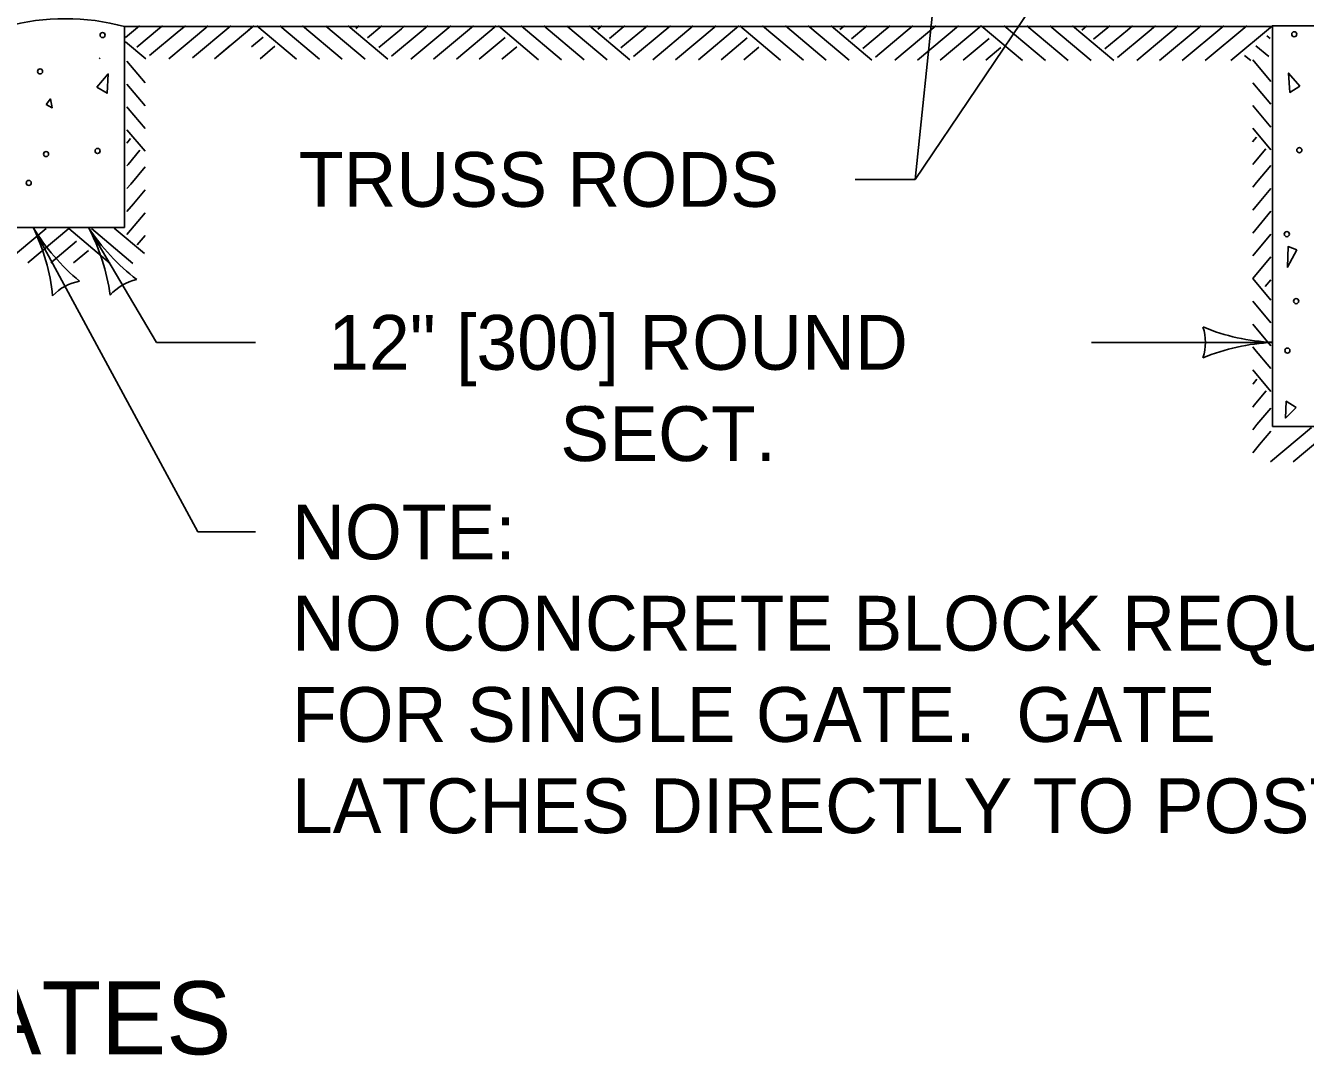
# Model space of a CAD drawing. Extents: x 49973.1 to 50021, y 49987.6 to 50015.4.
# Drawn here: x 50005.847 to 50007.249, y 49993.862 to 49994.99 of the extents above; entities that cross this region are included whole.
import ezdxf

# ---------------------------------------------------------------- set-up
doc = ezdxf.new("R2010")
doc.units = 0
for name, color, linetype in [('Level 1', 7, 'Continuous'), ('Level 2', 7, 'Continuous'), ('Level 3', 7, 'Continuous')]:
    doc.layers.add(name, color=color, linetype=linetype)

msp = doc.modelspace()

# ---------------------------------------------------------------- linework, layer by layer
at = {"layer": 'Level 1'}
for p, q in [((50007.2132, 49994.9895), (50005.9553, 49994.9895)), ((50005.9557, 49994.9894), (50005.9557, 49994.7693)), ((50005.9568, 49994.9774), (50005.9722, 49994.9902)), ((50005.9693, 49994.9669), (50005.9939, 49994.9875)), ((50005.9832, 49994.9575), (50006.0155, 49994.9846)), ((50005.9939, 49994.9875), (50005.9972, 49994.9902)), ((50006.0041, 49994.9541), (50006.0356, 49994.9804)), ((50006.0155, 49994.9846), (50006.0223, 49994.9902)), ((50006.0302, 49994.955), (50006.0723, 49994.9902)), ((50006.0356, 49994.9804), (50006.0473, 49994.9902)), ((50006.0541, 49994.9541), (50006.0972, 49994.9902)), ((50006.0915, 49994.9854), (50006.0972, 49994.9902)), ((50006.0946, 49994.9671), (50006.1075, 49994.9779)), ((50006.1442, 49994.9536), (50006.1007, 49994.9902)), ((50006.1692, 49994.9536), (50006.1257, 49994.9902)), ((50006.1942, 49994.9536), (50006.1507, 49994.9902)), ((50006.2192, 49994.9536), (50006.1762, 49994.9897)), ((50006.2442, 49994.9536), (50006.2007, 49994.9902)), ((50006.2092, 49994.9871), (50006.2129, 49994.9902)), ((50006.2219, 49994.9769), (50006.2376, 49994.99)), ((50006.2344, 49994.9664), (50006.259, 49994.987)), ((50006.2483, 49994.957), (50006.2806, 49994.9841)), ((50006.259, 49994.987), (50006.2629, 49994.9902)), ((50006.2692, 49994.9536), (50006.313, 49994.9902)), ((50006.2806, 49994.9841), (50006.288, 49994.9902)), ((50006.2942, 49994.9536), (50006.338, 49994.9902)), ((50006.3192, 49994.9536), (50006.3629, 49994.9902)), ((50006.3442, 49994.9536), (50006.3726, 49994.9774)), ((50006.4093, 49994.9531), (50006.3652, 49994.9902)), ((50006.4343, 49994.9531), (50006.3902, 49994.9902)), ((50006.4593, 49994.9531), (50006.4152, 49994.9902)), ((50006.4413, 49994.9892), (50006.4402, 49994.9902)), ((50006.4843, 49994.9531), (50006.4413, 49994.9892)), ((50006.5093, 49994.9531), (50006.4652, 49994.9902)), ((50006.4743, 49994.9866), (50006.4786, 49994.9902)), ((50006.487, 49994.9764), (50006.5027, 49994.9895)), ((50006.4995, 49994.9659), (50006.5241, 49994.9865)), ((50006.5027, 49994.9895), (50006.5036, 49994.9902)), ((50006.5134, 49994.9565), (50006.5457, 49994.9836)), ((50006.5241, 49994.9865), (50006.5286, 49994.9902)), ((50006.5343, 49994.9531), (50006.5787, 49994.9902)), ((50006.5457, 49994.9836), (50006.5537, 49994.9902)), ((50006.5593, 49994.9531), (50006.6037, 49994.9902)), ((50006.5843, 49994.9531), (50006.6286, 49994.9902)), ((50006.6093, 49994.9531), (50006.6377, 49994.9769)), ((50006.6744, 49994.9526), (50006.6297, 49994.9902)), ((50006.6994, 49994.9526), (50006.6547, 49994.9902)), ((50006.7244, 49994.9526), (50006.6797, 49994.9902)), ((50006.7064, 49994.9887), (50006.7047, 49994.9902)), ((50006.7494, 49994.9526), (50006.7064, 49994.9887)), ((50006.7744, 49994.9526), (50006.7297, 49994.9902)), ((50006.7394, 49994.9861), (50006.7444, 49994.9903)), ((50006.7521, 49994.9759), (50006.7678, 49994.989)), ((50006.7646, 49994.9654), (50006.7892, 49994.986)), ((50006.7678, 49994.989), (50006.7693, 49994.9902)), ((50006.7785, 49994.956), (50006.8108, 49994.9831)), ((50006.7892, 49994.986), (50006.7943, 49994.9902)), ((50006.7994, 49994.9526), (50006.8444, 49994.9902)), ((50006.8108, 49994.9831), (50006.8194, 49994.9902)), ((50006.8244, 49994.9526), (50006.8694, 49994.9902)), ((50006.8494, 49994.9526), (50006.8942, 49994.9902)), ((50006.9395, 49994.9521), (50006.8942, 49994.9902)), ((50006.9645, 49994.9521), (50006.9192, 49994.9902)), ((50006.9895, 49994.9521), (50006.9442, 49994.9902)), ((50006.9715, 49994.9882), (50006.9692, 49994.9902)), ((50007.0145, 49994.9521), (50006.9715, 49994.9882)), ((50007.0395, 49994.9521), (50006.9942, 49994.9902)), ((50007.0045, 49994.9856), (50007.0095, 49994.9898)), ((50007.0095, 49994.9898), (50007.01, 49994.9902)), ((50007.0172, 49994.9754), (50007.0329, 49994.9885)), ((50007.0297, 49994.9649), (50007.0543, 49994.9855)), ((50007.0329, 49994.9885), (50007.035, 49994.9902)), ((50007.0436, 49994.9555), (50007.0759, 49994.9826)), ((50007.0543, 49994.9855), (50007.06, 49994.9902)), ((50007.0645, 49994.9521), (50007.11, 49994.9902)), ((50007.0759, 49994.9826), (50007.0851, 49994.9902)), ((50007.0895, 49994.9521), (50007.135, 49994.9902)), ((50007.1145, 49994.9521), (50007.1599, 49994.9902)), ((50007.1395, 49994.9521), (50007.185, 49994.9902)), ((50007.1677, 49994.9522), (50007.2132, 49994.9903)), ((50007.2106, 49994.9764), (50007.2071, 49994.9793)), ((50007.2132, 49994.9903), (50007.2132, 49994.5512)), ((50007.2132, 49994.9903), (50007.3432, 49994.9903)), ((50005.9791, 49994.9541), (50005.9569, 49994.9728)), ((50006.0541, 49994.9541), (50006.0715, 49994.9687)), ((50006.1041, 49994.9541), (50006.1204, 49994.9678)), ((50006.3692, 49994.9536), (50006.3855, 49994.9673)), ((50006.6343, 49994.9531), (50006.6506, 49994.9668)), ((50006.8744, 49994.9526), (50006.9028, 49994.9764)), ((50006.8994, 49994.9526), (50006.9157, 49994.9663)), ((50007.2094, 49994.9564), (50007.195, 49994.9684)), ((50005.9291, 49994.9541), (50005.9278, 49994.9552)), ((50005.9782, 49994.9277), (50005.9583, 49994.9514)), ((50007.1895, 49994.9521), (50007.1827, 49994.9578)), ((50007.2115, 49994.9292), (50007.1916, 49994.9529)), ((50005.9782, 49994.9027), (50005.9583, 49994.9264)), ((50007.2115, 49994.9042), (50007.1916, 49994.9279)), ((50005.9598, 49994.8997), (50005.9583, 49994.9014)), ((50005.9782, 49994.8777), (50005.9598, 49994.8997)), ((50007.1931, 49994.9012), (50007.1916, 49994.9029)), ((50007.2115, 49994.8792), (50007.1931, 49994.9012)), ((50005.9624, 49994.8667), (50005.9582, 49994.8617)), ((50005.9782, 49994.8527), (50005.9583, 49994.8764)), ((50007.1957, 49994.8682), (50007.1915, 49994.8632)), ((50007.2115, 49994.8542), (50007.1916, 49994.8779)), ((50005.9726, 49994.854), (50005.9595, 49994.8383)), ((50007.2059, 49994.8555), (50007.1928, 49994.8398)), ((50005.9595, 49994.8383), (50005.9583, 49994.8368)), ((50007.1928, 49994.8398), (50007.1916, 49994.8383)), ((50007.2115, 49994.8371), (50007.1958, 49994.8184)), ((50005.9782, 49994.8356), (50005.9625, 49994.8169)), ((50005.9625, 49994.8169), (50005.9583, 49994.8118)), ((50005.9782, 49994.8105), (50005.9654, 49994.7953)), ((50007.1958, 49994.8184), (50007.1916, 49994.8133)), ((50007.2115, 49994.812), (50007.1987, 49994.7968)), ((50005.9654, 49994.7953), (50005.9583, 49994.7867)), ((50007.1987, 49994.7968), (50007.1916, 49994.7882)), ((50005.9782, 49994.7855), (50005.9583, 49994.7617)), ((50007.2115, 49994.787), (50007.1916, 49994.7632)), ((50005.8248, 49994.7305), (50005.8698, 49994.7681)), ((50005.8257, 49994.7693), (50005.9557, 49994.7693)), ((50005.8498, 49994.7305), (50005.8946, 49994.7681)), ((50005.9399, 49994.73), (50005.8946, 49994.7681)), ((50005.9649, 49994.73), (50005.9196, 49994.7681)), ((50005.9774, 49994.7406), (50005.9443, 49994.7684)), ((50005.8748, 49994.7305), (50005.9032, 49994.7543)), ((50005.9782, 49994.7605), (50005.9695, 49994.7501)), ((50007.2115, 49994.762), (50007.1916, 49994.7382)), ((50005.8998, 49994.7305), (50005.9161, 49994.7442)), ((50007.2115, 49994.7371), (50007.1916, 49994.7134)), ((50007.2115, 49994.6897), (50007.1916, 49994.7134)), ((50007.2115, 49994.712), (50007.2054, 49994.7048)), ((50007.2115, 49994.6647), (50007.1916, 49994.6884)), ((50007.2115, 49994.6397), (50007.1916, 49994.6634)), ((50007.1936, 49994.6361), (50007.1916, 49994.6384)), ((50007.2115, 49994.6147), (50007.1936, 49994.6361)), ((50007.2115, 49994.5897), (50007.1916, 49994.6134)), ((50007.1962, 49994.6031), (50007.192, 49994.5981)), ((50007.192, 49994.5981), (50007.1916, 49994.5976)), ((50007.2064, 49994.5904), (50007.1933, 49994.5747)), ((50007.1933, 49994.5747), (50007.1916, 49994.5726)), ((50007.2115, 49994.5714), (50007.1963, 49994.5533)), ((50007.1963, 49994.5533), (50007.1916, 49994.5476)), ((50007.2115, 49994.5463), (50007.1992, 49994.5317)), ((50007.2111, 49994.5124), (50007.2561, 49994.55)), ((50007.3432, 49994.5512), (50007.2132, 49994.5512)), ((50007.2361, 49994.5124), (50007.2809, 49994.55)), ((50007.1992, 49994.5317), (50007.1916, 49994.5225))]:
    msp.add_line(p, q, dxfattribs=at)
for points in [[(50005.9255, 49994.9231), (50005.9379, 49994.9375), (50005.9365, 49994.9163)], [(50007.2434, 49994.924), (50007.231, 49994.9384), (50007.2324, 49994.9172)], [(50005.8697, 49994.9039), (50005.8745, 49994.9101), (50005.8765, 49994.9005)], [(50007.24, 49994.7449), (50007.2304, 49994.7484), (50007.2297, 49994.7257)], [(50007.2393, 49994.572), (50007.2283, 49994.5789), (50007.2276, 49994.5604)]]:
    msp.add_lwpolyline(points, close=True, dxfattribs=at)
for centre in [(50005.9317, 49994.98), (50007.2372, 49994.9809), (50005.8631, 49994.9402), (50005.8697, 49994.8497), (50005.9262, 49994.8531), (50007.2427, 49994.854), (50005.8507, 49994.8181), (50007.229, 49994.762), (50007.2392, 49994.6886), (50007.2296, 49994.6344)]:
    msp.add_circle(centre, 0.00279, dxfattribs=at)
msp.add_arc((50005.8907, 49994.7481), 0.2499, 74.9261, 105.0737, dxfattribs=at)
at = {"layer": 'Level 3'}
for p, q in [((50006.9054, 49995.6337), (50006.8219, 49994.8219)), ((50006.8219, 49994.8219), (50007.0348, 49995.1377)), ((50006.8219, 49994.8219), (50006.756, 49994.8219)), ((50005.8555, 49994.7693), (50006.0359, 49994.4358)), ((50005.9908, 49994.6434), (50005.9161, 49994.7693)), ((50006.0991, 49994.6434), (50005.9908, 49994.6434)), ((50007.0149, 49994.6434), (50007.2132, 49994.6434)), ((50006.0991, 49994.4358), (50006.0359, 49994.4358))]:
    msp.add_line(p, q, dxfattribs=at)
for centre, radius, start, end in [((50005.6558, 49994.6717), 0.2223, 5.8684, 26.0519), ((50006.0547, 49994.8902), 0.233, 211.2397, 230.4895), ((50005.7197, 49994.6651), 0.2223, 7.7836, 27.9671), ((50006.1112, 49994.8968), 0.233, 213.1549, 232.4047), ((50005.9165, 49994.6566), 0.0548, 100.5512, 136.2735), ((50005.9808, 49994.6587), 0.0548, 102.4664, 138.1887), ((50007.2224, 49994.8656), 0.2223, 247.456, 267.6395), ((50007.085, 49994.6434), 0.0548, 342.1388, 17.8612), ((50007.2247, 49994.4107), 0.233, 92.8273, 112.0772)]:
    msp.add_arc(centre, radius, start, end, dxfattribs=at)

# ---------------------------------------------------------------- texts
at = {"layer": 'Level 2'}
for s, height, p in [('TRUSS RODS', 0.06, (50006.1466, 49994.7919)), ('12" [300] ROUND', 0.06, (50006.1789, 49994.6134)), ('SECT.', 0.06, (50006.4331, 49994.5134)), ('NOTE:', 0.06, (50006.1391, 49994.4058)), ('NO CONCRETE BLOCK REQUIRED', 0.06, (50006.1391, 49994.3058)), ('FOR SINGLE GATE.  GATE', 0.06, (50006.1391, 49994.2058)), ('LATCHES DIRECTLY TO POST.', 0.06, (50006.1391, 49994.1058)), ('GATES', 0.08, (50005.7101, 49993.8635))]:
    msp.add_text(s, height=height, dxfattribs=at).set_placement(p)

doc.saveas('drawing.dxf')
